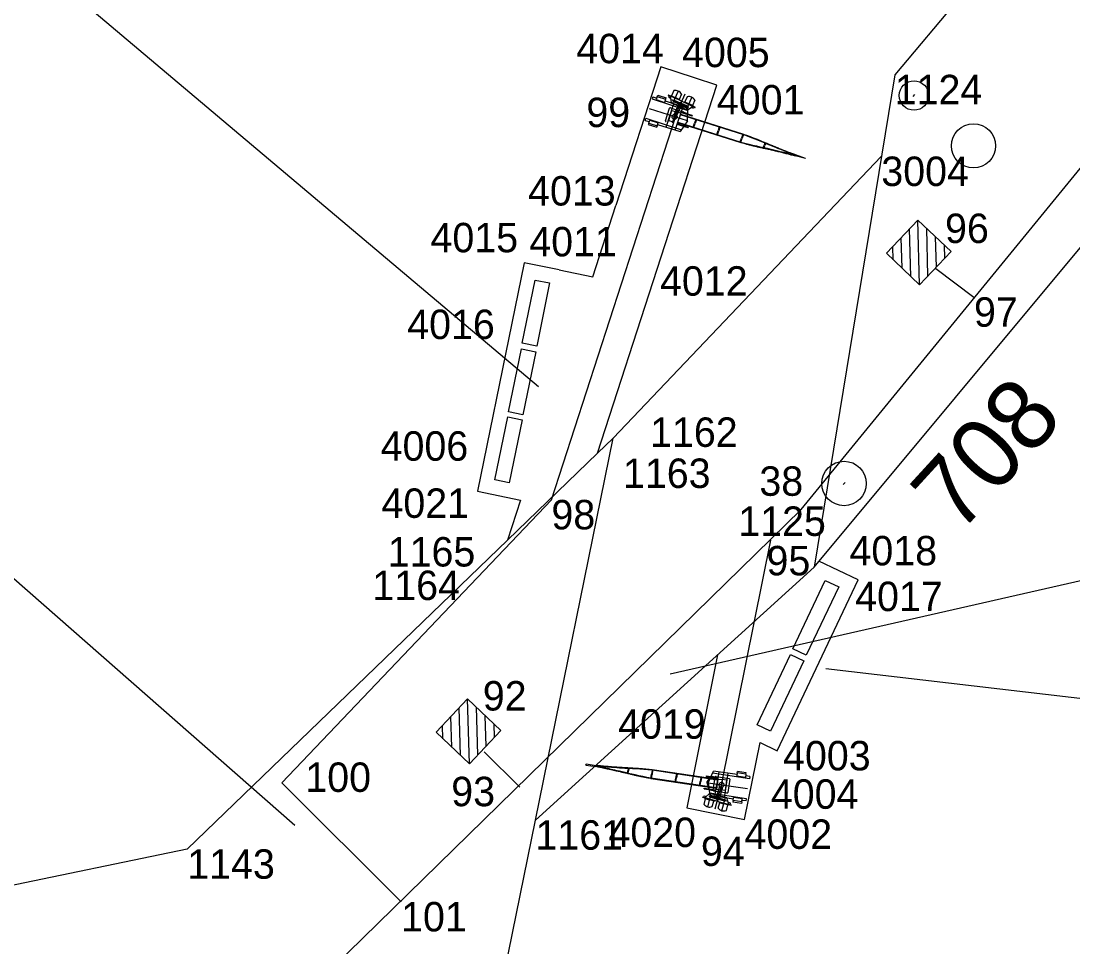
# Model space of a CAD drawing. Extents: x -678683 to -677755, y -1006946 to -1005971.
# Drawn here: x -678303.02 to -678267.29, y -1006518.8 to -1006487.34 of the extents above; entities that cross this region are included whole.
import ezdxf

# ---------------------------------------------------------------- set-up
doc = ezdxf.new("R2010")
doc.units = 0
for name, color, linetype in [('Default', 7, 'Continuous'), ('Dočasný zábor - do 1 roku', 7, 'Continuous'), ('Dočasný zábor_body', 7, 'Continuous'), ('OSY', 7, 'Continuous'), ('SSZT nové - lomové body', 7, 'Continuous'), ('SSZT_nové', 7, 'Continuous'), ('Stávající ŽBP', 7, 'Continuous'), ('SŽDC', 7, 'Continuous'), ('SŽDC - body', 7, 'Continuous'), ('Trvalý zábor', 7, 'Continuous'), ('Trvalý zábor - body', 7, 'Continuous'), ('Vrstva 7', 7, 'Continuous')]:
    doc.layers.add(name, color=color, linetype=linetype)

# ---------------------------------------------------------------- blocks, each defined once
blk = doc.blocks.new('AZD97_VYSTRAZNIK')
at = {"layer": 'Default'}
for p, q in [((-34, -7.5), (-24, 8)), ((-24, 8), (0, 8)), ((-20, 2), (0, 2)), ((24, 8), (0, 8)), ((20, 2), (0, 2)), ((34, -7.5), (24, 8)), ((0, -7.5), (-40, -7.5)), ((-40, -7.5), (-40, -8)), ((0, -8), (-40, -8)), ((-36.9, -7.5), (-36.9, -3)), ((-36.9, -3), (-31.1, -3)), ((-34, -8), (-34, -9.5)), ((-34, -9.5), (-20, -9.5)), ((-31.5, -25.2), (-31.5, -9.5)), ((-20, -2), (0, -2)), ((-6, -9.5), (-20, -9.5)), ((-8.5, -25.2), (-8.5, -9.5)), ((-6, -8), (-6, -9.5)), ((20, -2), (0, -2)), ((0, -7.5), (40, -7.5)), ((0, -8), (40, -8)), ((6, -8), (6, -9.5)), ((6, -9.5), (20, -9.5)), ((8.5, -25.2), (8.5, -9.5)), ((34, -9.5), (20, -9.5)), ((36.9, -3), (31.1, -3)), ((31.5, -25.2), (31.5, -9.5)), ((34, -8), (34, -9.5)), ((36.9, -7.5), (36.9, -3)), ((40, -7.5), (40, -8))]:
    blk.add_line(p, q, dxfattribs=at)
for centre in [(-20, 0), (20, 0)]:
    blk.add_circle(centre, 2, dxfattribs=at)
for centre, start, end in [((-20, -9.5), 233.8612, 270), ((-20, -9.5), 270, 306.1388), ((20, -9.5), 233.8612, 270), ((20, -9.5), 270, 306.1388)]:
    blk.add_arc(centre, 19.5, start, end, dxfattribs=at)
at = {"layer": 'OSY'}
for p, q in [((-24.8, 0), (25.7, 0)), ((-20, -29), (-20, 8)), ((0, 8), (0, -29.7)), ((20, -29), (20, 8))]:
    blk.add_line(p, q, dxfattribs=at)
blk = doc.blocks.new('AZD97_DRZAK')
at = {"layer": 'Default'}
for p, q in [((-4, -5.3), (-4, -38.3)), ((-0.7, -7.4), (-0.7, -6.6)), ((0.6, -7.4), (0.6, -6.6)), ((4, -5.3), (4, -38.3))]:
    blk.add_line(p, q, dxfattribs=at)
for centre, radius, start, end in [((0, 0), 6.65, 233.0223, 306.9777), ((0, 0), 7.5, 237.769, 270), ((0, 0), 7.5, 270, 302.231), ((0, -38.3), 4, 180, 0)]:
    blk.add_arc(centre, radius, start, end, dxfattribs=at)
at = {"layer": 'OSY'}
for p, q in [((0, 6.6), (0, -42.3)), ((-6.7, 0), (6.6, 0)), ((-4, -38.3), (4, -38.3))]:
    blk.add_line(p, q, dxfattribs=at)
blk = doc.blocks.new('AZD99_KŘÍDLA')
at = {"layer": 'Default'}
for p, q in [((-46, 0), (-34, 42)), ((47, 42), (-34, 42)), ((-16, 42), (-16, 0)), ((47, 47.5), (47, 52.5)), ((77, 52.5), (47, 52.5)), ((77, 47.5), (47, 47.5)), ((47, 47.5), (47, 36.5)), ((77, 36.5), (47, 36.5)), ((77, 47.5), (77, 52.5)), ((77, 47.5), (77, 36.5)), ((91, 42), (77, 42)), ((91, 42), (91, 34.5)), ((-56, 22), (-16, 22)), ((-56, 22), (-56, 20)), ((-56, 20), (-16, 20)), ((-46, 0), (-34, -42)), ((91, 34.5), (-36.2, 34.5)), ((-16, -42), (-16, 0)), ((-56, -20), (-16, -20)), ((-56, -22), (-56, -20)), ((-56, -22), (-16, -22)), ((91, -34.5), (-36.2, -34.5)), ((91, -42), (91, -34.5)), ((47, -42), (-34, -42)), ((77, -36.5), (47, -36.5)), ((47, -47.5), (47, -36.5)), ((77, -47.5), (47, -47.5)), ((47, -47.5), (47, -52.5)), ((77, -52.5), (47, -52.5)), ((77, -47.5), (77, -36.5)), ((91, -42), (77, -42)), ((77, -47.5), (77, -52.5))]:
    blk.add_line(p, q, dxfattribs=at)
at = {"layer": 'OSY'}
for p, q in [((16, 42), (16, -42)), ((-46, 0), (89, 0)), ((0, 21.9), (0, -22.2))]:
    blk.add_line(p, q, dxfattribs=at)

msp = doc.modelspace()

# ---------------------------------------------------------------- linework, layer by layer
at = {"layer": 'Dočasný zábor - do 1 roku'}
for p, q in [((-678281.283, -1006488.901), (-678282.811, -1006493.613)), ((-678280.139, -1006489.272), (-678281.283, -1006488.901)), ((-678279.381, -1006489.517), (-678280.139, -1006489.272)), ((-678283.435, -1006502.026), (-678279.381, -1006489.517)), ((-678283.595, -1006496.033), (-678282.811, -1006493.613)), ((-678285.921, -1006495.555), (-678286.341, -1006497.603)), ((-678284.743, -1006495.797), (-678285.921, -1006495.555)), ((-678284.743, -1006495.797), (-678283.595, -1006496.033)), ((-678286.341, -1006497.603), (-678287.515, -1006503.316)), ((-678287.515, -1006503.316), (-678286.053, -1006503.616)), ((-678286.053, -1006503.616), (-678286.495, -1006504.981)), ((-678274.577, -1006506.322), (-678275.913, -1006505.69)), ((-678277.328, -1006512.133), (-678274.577, -1006506.322)), ((-678279.356, -1006508.868), (-678280.402, -1006514.072)), ((-678278.442, -1006514.466), (-678277.916, -1006511.854)), ((-678277.916, -1006511.854), (-678277.328, -1006512.133)), ((-678280.402, -1006514.072), (-678278.442, -1006514.466))]:
    msp.add_line(p, q, dxfattribs=at)
at = {"layer": 'Dočasný zábor_body'}
for p, q in [((-678281.283, -1006488.901), (-678281.283, -1006488.901)), ((-678280.139, -1006489.272), (-678280.139, -1006489.272)), ((-678279.381, -1006489.517), (-678279.381, -1006489.517)), ((-678282.811, -1006493.613), (-678282.811, -1006493.613)), ((-678282.811, -1006493.613), (-678282.811, -1006493.613)), ((-678285.921, -1006495.555), (-678285.921, -1006495.555)), ((-678284.743, -1006495.797), (-678284.743, -1006495.797)), ((-678283.595, -1006496.033), (-678283.595, -1006496.033)), ((-678286.341, -1006497.603), (-678286.341, -1006497.603)), ((-678287.515, -1006503.316), (-678287.515, -1006503.316)), ((-678286.053, -1006503.616), (-678286.053, -1006503.616)), ((-678275.913, -1006505.69), (-678275.913, -1006505.69)), ((-678274.577, -1006506.322), (-678274.577, -1006506.322)), ((-678279.356, -1006508.868), (-678279.356, -1006508.868)), ((-678277.916, -1006511.854), (-678277.916, -1006511.854)), ((-678277.328, -1006512.133), (-678277.328, -1006512.133)), ((-678280.402, -1006514.072), (-678280.402, -1006514.072)), ((-678278.442, -1006514.466), (-678278.442, -1006514.466))]:
    msp.add_line(p, q, dxfattribs=at)
at = {"layer": 'SSZT nové - lomové body'}
for p, q in [((-678280.64, -1006490.16), (-678280.64, -1006490.16)), ((-678271.945, -1006495.744), (-678271.945, -1006495.744)), ((-678270.648, -1006496.728), (-678270.648, -1006496.728)), ((-678285, -1006503.611), (-678285, -1006503.611)), ((-678276.518, -1006503.932), (-678276.518, -1006503.932)), ((-678277.553, -1006504.979), (-678277.553, -1006504.979)), ((-678287.288, -1006512.164), (-678287.288, -1006512.164)), ((-678294.158, -1006513.226), (-678294.158, -1006513.226)), ((-678279.225, -1006513.289), (-678279.225, -1006513.289)), ((-678286.073, -1006513.373), (-678286.073, -1006513.373)), ((-678290.107, -1006517.269), (-678290.107, -1006517.269))]:
    msp.add_line(p, q, dxfattribs=at)
at = {"layer": 'SSZT_nové'}
for p, q in [((-678319.244, -1006471.244), (-678285.442, -1006499.753)), ((-678285, -1006503.611), (-678280.64, -1006490.16)), ((-678281.125, -1006490.734), (-678280.987, -1006490.305)), ((-678281.014, -1006490.717), (-678280.907, -1006490.383)), ((-678280.956, -1006490.289), (-678280.754, -1006490.354)), ((-678280.907, -1006490.383), (-678280.764, -1006490.429)), ((-678280.622, -1006490.475), (-678280.764, -1006490.429)), ((-678280.754, -1006490.354), (-678280.527, -1006490.426)), ((-678280.593, -1006490.421), (-678280.666, -1006490.645)), ((-678280.371, -1006490.492), (-678280.593, -1006490.421)), ((-678281.014, -1006490.717), (-678280.871, -1006490.762)), ((-678280.713, -1006490.79), (-678278.571, -1006491.471)), ((-678280.709, -1006490.777), (-678278.566, -1006491.457)), ((-678280.619, -1006490.502), (-678280.666, -1006490.646)), ((-678280.623, -1006490.515), (-678278.481, -1006491.196)), ((-678280.619, -1006490.502), (-678278.477, -1006491.183)), ((-678280.096, -1006490.683), (-678280.139, -1006490.814)), ((-678280.074, -1006490.69), (-678280.117, -1006490.821)), ((-678280.181, -1006490.944), (-678280.139, -1006490.814)), ((-678280.159, -1006490.951), (-678280.117, -1006490.821)), ((-678279.385, -1006491.197), (-678279.342, -1006491.067)), ((-678279.363, -1006491.204), (-678279.32, -1006491.074)), ((-678279.3, -1006490.936), (-678279.342, -1006491.067)), ((-678279.278, -1006490.943), (-678279.32, -1006491.074)), ((-678278.588, -1006491.451), (-678278.546, -1006491.32)), ((-678278.566, -1006491.457), (-678278.524, -1006491.327)), ((-678278.503, -1006491.189), (-678278.546, -1006491.32)), ((-678278.481, -1006491.196), (-678278.524, -1006491.327)), ((-678277.751, -1006491.484), (-678277.777, -1006491.564)), ((-678277.729, -1006491.493), (-678277.755, -1006491.571)), ((-678277.803, -1006491.644), (-678277.777, -1006491.564)), ((-678277.78, -1006491.649), (-678277.755, -1006491.571)), ((-678277.014, -1006491.829), (-678277.008, -1006491.808)), ((-678277.001, -1006491.788), (-678277.008, -1006491.808)), ((-678276.992, -1006491.834), (-678276.986, -1006491.815)), ((-678276.979, -1006491.796), (-678276.986, -1006491.815)), ((-678276.366, -1006492.017), (-678276.717, -1006491.922)), ((-678276.366, -1006492.017), (-678276.705, -1006491.883)), ((-678272.494, -1006496.303), (-678272.553, -1006494.103)), ((-678273.093, -1006495.735), (-678273.121, -1006494.702)), ((-678272.793, -1006496.019), (-678272.837, -1006494.402)), ((-678272.21, -1006496.003), (-678272.254, -1006494.386)), ((-678271.926, -1006495.703), (-678271.954, -1006494.671)), ((-678273.392, -1006495.451), (-678273.405, -1006495.002)), ((-678271.643, -1006495.404), (-678271.655, -1006494.954)), ((-678271.945, -1006495.744), (-678270.648, -1006496.728)), ((-678311.879, -1006498.718), (-678293.712, -1006514.658)), ((-678285, -1006503.611), (-678294.158, -1006513.226)), ((-678280.963, -1006509.518), (-678258.777, -1006504.475)), ((-678279.225, -1006513.289), (-678277.553, -1006504.979)), ((-678275.682, -1006509.338), (-678242.476, -1006513.226)), ((-678287.788, -1006512.573), (-678287.848, -1006510.373)), ((-678288.088, -1006512.289), (-678288.132, -1006510.673)), ((-678287.505, -1006512.273), (-678287.549, -1006510.657)), ((-678288.388, -1006512.005), (-678288.416, -1006510.973)), ((-678287.221, -1006511.974), (-678287.249, -1006510.941)), ((-678288.687, -1006511.722), (-678288.699, -1006511.272)), ((-678286.937, -1006511.674), (-678286.949, -1006511.224)), ((-678287.288, -1006512.164), (-678286.073, -1006513.373)), ((-678283.828, -1006512.594), (-678283.826, -1006512.581)), ((-678283.826, -1006512.581), (-678283.484, -1006512.632)), ((-678283.83, -1006512.608), (-678283.832, -1006512.621)), ((-678283.832, -1006512.621), (-678283.49, -1006512.672)), ((-678283.205, -1006512.714), (-678283.202, -1006512.694)), ((-678283.199, -1006512.674), (-678283.202, -1006512.694)), ((-678283.182, -1006512.718), (-678283.179, -1006512.698)), ((-678283.176, -1006512.677), (-678283.179, -1006512.698)), ((-678282.416, -1006512.894), (-678282.404, -1006512.813)), ((-678282.391, -1006512.732), (-678282.404, -1006512.813)), ((-678282.394, -1006512.899), (-678282.381, -1006512.816)), ((-678282.368, -1006512.733), (-678282.381, -1006512.816)), ((-678281.627, -1006513.067), (-678281.605, -1006512.931)), ((-678281.584, -1006512.795), (-678281.605, -1006512.931)), ((-678281.604, -1006513.071), (-678281.583, -1006512.935)), ((-678279.361, -1006513.126), (-678281.584, -1006512.795)), ((-678281.562, -1006512.799), (-678281.583, -1006512.935)), ((-678279.359, -1006513.112), (-678281.582, -1006512.782)), ((-678280.758, -1006512.918), (-678280.779, -1006513.054)), ((-678280.735, -1006512.922), (-678280.756, -1006513.057)), ((-678294.158, -1006513.226), (-678290.107, -1006517.269)), ((-678279.405, -1006513.411), (-678281.629, -1006513.081)), ((-678279.403, -1006513.397), (-678281.627, -1006513.067)), ((-678280.8, -1006513.19), (-678280.779, -1006513.054)), ((-678280.777, -1006513.193), (-678280.756, -1006513.057)), ((-678279.973, -1006513.313), (-678279.952, -1006513.177)), ((-678279.931, -1006513.041), (-678279.952, -1006513.177)), ((-678279.951, -1006513.316), (-678279.929, -1006513.18)), ((-678279.908, -1006513.044), (-678279.929, -1006513.18)), ((-678279.724, -1006513.211), (-678279.575, -1006512.994)), ((-678279.724, -1006513.211), (-678279.648, -1006513.461)), ((-678279.575, -1006512.994), (-678279.346, -1006513.028)), ((-678279.505, -1006513.472), (-678279.438, -1006513.027)), ((-678279.418, -1006513.495), (-678279.382, -1006513.262)), ((-678279.409, -1006513.006), (-678279.174, -1006513.042)), ((-678279.405, -1006513.411), (-678279.382, -1006513.262)), ((-678279.346, -1006513.092), (-678279.398, -1006513.438)), ((-678279.346, -1006513.028), (-678279.382, -1006513.261)), ((-678279.359, -1006513.112), (-678279.382, -1006513.262)), ((-678279.346, -1006513.092), (-678279.198, -1006513.114)), ((-678279.05, -1006513.136), (-678279.198, -1006513.114)), ((-678279.174, -1006513.042), (-678278.964, -1006513.073)), ((-678279.05, -1006513.136), (-678279.102, -1006513.482)), ((-678278.943, -1006513.102), (-678279.01, -1006513.547)), ((-678279.648, -1006513.461), (-678279.418, -1006513.495)), ((-678279.249, -1006513.536), (-678279.484, -1006513.501)), ((-678279.398, -1006513.438), (-678279.25, -1006513.46)), ((-678279.102, -1006513.482), (-678279.25, -1006513.46)), ((-678279.039, -1006513.568), (-678279.249, -1006513.536))]:
    msp.add_line(p, q, dxfattribs=at)
for points in [[(-678276.518, -1006503.932), (-678257.417, -1006480.575), (-678238.833, -1006456.747), (-678223.794, -1006437.464), (-678213.311, -1006424.022), (-678199.433, -1006408.271)], [(-678506.624, -1006791.938), (-678466.12, -1006753.227), (-678449.329, -1006728.75), (-678428.753, -1006695.612), (-678421.07, -1006681.971), (-678401.666, -1006635.236), (-678393.87, -1006623.108), (-678390.132, -1006617.261), (-678380.001, -1006603.755), (-678359.836, -1006584.701), (-678339.66, -1006565.68), (-678276.518, -1006503.932), (-678276.518, -1006503.932)]]:
    msp.add_lwpolyline(points, dxfattribs=at)
for points in [[(-678273.623, -1006495.233), (-678272.553, -1006494.103), (-678271.424, -1006495.173), (-678272.494, -1006496.303)], [(-678285.555, -1006496.141), (-678285.061, -1006496.242), (-678285.501, -1006498.384), (-678285.995, -1006498.282)], [(-678286.022, -1006498.481), (-678285.528, -1006498.583), (-678285.968, -1006500.724), (-678286.462, -1006500.623)], [(-678286.485, -1006500.785), (-678285.991, -1006500.887), (-678286.431, -1006503.028), (-678286.925, -1006502.927)], [(-678275.699, -1006506.344), (-678275.243, -1006506.56), (-678276.345, -1006508.888), (-678276.8, -1006508.672)], [(-678276.878, -1006508.866), (-678276.422, -1006509.082), (-678277.554, -1006511.472), (-678278.009, -1006511.257)], [(-678288.918, -1006511.503), (-678287.848, -1006510.373), (-678286.718, -1006511.443), (-678287.788, -1006512.573)]]:
    msp.add_lwpolyline(points, close=True, dxfattribs=at)
for centre in [(-678280.818, -1006490.596), (-678279.224, -1006513.287)]:
    msp.add_circle(centre, 0.0831, dxfattribs=at)
for centre, start, end in [((-678280.964, -1006490.313), 72.2544, 162.2544), ((-678280.535, -1006490.45), 342.2544, 72.2544), ((-678281.101, -1006490.741), 162.2544, 252.2544), ((-678279.413, -1006513.031), 81.4339, 171.4339), ((-678278.968, -1006513.098), 351.4339, 81.4339), ((-678279.48, -1006513.476), 171.4339, 261.4339), ((-678279.035, -1006513.543), 261.4339, 351.4339)]:
    msp.add_arc(centre, 0.025, start, end, dxfattribs=at)
for points in [[(-678278.568, -1006491.47), (-678278.485, -1006491.492), (-678278.402, -1006491.515), (-678278.275, -1006491.547), (-678278.232, -1006491.558), (-678278.146, -1006491.58), (-678278.103, -1006491.59), (-678277.974, -1006491.62), (-678277.888, -1006491.639), (-678277.727, -1006491.675), (-678277.652, -1006491.691), (-678277.499, -1006491.726), (-678277.419, -1006491.744), (-678277.261, -1006491.781), (-678277.182, -1006491.8), (-678277.056, -1006491.832), (-678277.01, -1006491.844), (-678276.917, -1006491.868), (-678276.871, -1006491.881), (-678276.788, -1006491.903), (-678276.752, -1006491.913), (-678276.716, -1006491.923)], [(-678278.566, -1006491.457), (-678278.198, -1006491.553), (-678277.512, -1006491.709), (-678277.014, -1006491.829), (-678276.713, -1006491.909), (-678278.566, -1006491.457), (-678276.713, -1006491.909)], [(-678278.481, -1006491.197), (-678278.126, -1006491.331), (-678277.477, -1006491.599), (-678277.001, -1006491.788), (-678276.709, -1006491.896), (-678278.481, -1006491.197), (-678276.709, -1006491.896)], [(-678278.476, -1006491.185), (-678278.395, -1006491.214), (-678278.314, -1006491.244), (-678278.191, -1006491.291), (-678278.15, -1006491.307), (-678278.068, -1006491.339), (-678278.027, -1006491.355), (-678277.904, -1006491.405), (-678277.822, -1006491.439), (-678277.671, -1006491.503), (-678277.601, -1006491.532), (-678277.455, -1006491.593), (-678277.38, -1006491.624), (-678277.229, -1006491.685), (-678277.154, -1006491.715), (-678277.033, -1006491.761), (-678276.989, -1006491.778), (-678276.899, -1006491.812), (-678276.854, -1006491.829), (-678276.774, -1006491.858), (-678276.738, -1006491.871), (-678276.703, -1006491.884)], [(-678281.63, -1006513.079), (-678281.715, -1006513.063), (-678281.8, -1006513.046), (-678281.928, -1006513.02), (-678281.971, -1006513.011), (-678282.058, -1006512.992), (-678282.101, -1006512.982), (-678282.23, -1006512.953), (-678282.316, -1006512.932), (-678282.476, -1006512.894), (-678282.55, -1006512.876), (-678282.703, -1006512.839), (-678282.782, -1006512.82), (-678282.94, -1006512.784), (-678283.02, -1006512.767), (-678283.146, -1006512.74), (-678283.193, -1006512.73), (-678283.287, -1006512.711), (-678283.334, -1006512.702), (-678283.418, -1006512.686), (-678283.455, -1006512.679), (-678283.492, -1006512.672)], [(-678281.626, -1006513.066), (-678281.999, -1006512.991), (-678282.682, -1006512.83), (-678283.182, -1006512.718), (-678283.488, -1006512.659), (-678281.626, -1006513.066), (-678283.488, -1006512.659)], [(-678281.584, -1006512.796), (-678281.963, -1006512.76), (-678282.665, -1006512.715), (-678283.176, -1006512.677), (-678283.486, -1006512.645), (-678281.584, -1006512.796), (-678283.486, -1006512.645)], [(-678281.584, -1006512.783), (-678281.67, -1006512.774), (-678281.756, -1006512.765), (-678281.886, -1006512.753), (-678281.93, -1006512.749), (-678282.019, -1006512.742), (-678282.063, -1006512.739), (-678282.195, -1006512.729), (-678282.283, -1006512.724), (-678282.448, -1006512.714), (-678282.524, -1006512.71), (-678282.681, -1006512.701), (-678282.762, -1006512.696), (-678282.925, -1006512.684), (-678283.006, -1006512.678), (-678283.135, -1006512.667), (-678283.182, -1006512.662), (-678283.278, -1006512.653), (-678283.326, -1006512.648), (-678283.411, -1006512.639), (-678283.448, -1006512.635), (-678283.485, -1006512.631)]]:
    msp.add_open_spline(points, degree=3, dxfattribs=at)
at = {"layer": 'Stávající ŽBP'}
msp.add_line((-678275.096, -1006503.09), (-678275.028, -1006503.016), dxfattribs=at)
msp.add_circle((-678275.062, -1006503.053), 0.756, dxfattribs=at)
at = {"layer": 'SŽDC'}
for p, q in [((-678259.32, -1006472.44), (-678273.34, -1006489.17)), ((-678273.34, -1006489.17), (-678276.08, -1006505.89)), ((-678276.08, -1006505.89), (-678265.21, -1006492.84)), ((-678285.543, -1006514.493), (-678282.9, -1006501.51)), ((-678282.9, -1006501.51), (-678283.435, -1006502.026)), ((-678283.435, -1006502.026), (-678286.495, -1006504.981)), ((-678286.495, -1006504.981), (-678297.37, -1006515.48)), ((-678288.96, -1006531.28), (-678285.543, -1006514.493)), ((-678297.37, -1006515.48), (-678306.89, -1006517.45))]:
    msp.add_line(p, q, dxfattribs=at)
at = {"layer": 'SŽDC - body'}
for p, q in [((-678273.34, -1006489.17), (-678273.34, -1006489.17)), ((-678282.9, -1006501.51), (-678282.9, -1006501.51)), ((-678283.435, -1006502.026), (-678283.435, -1006502.026)), ((-678286.495, -1006504.981), (-678286.495, -1006504.981)), ((-678286.495, -1006504.981), (-678286.495, -1006504.981)), ((-678276.08, -1006505.89), (-678276.08, -1006505.89)), ((-678285.543, -1006514.493), (-678285.543, -1006514.493)), ((-678297.37, -1006515.48), (-678297.37, -1006515.48))]:
    msp.add_line(p, q, dxfattribs=at)
at = {"layer": 'Trvalý zábor'}
for p, q in [((-678282.9, -1006501.51), (-678273.795, -1006491.947)), ((-678276.08, -1006505.89), (-678285.543, -1006514.493))]:
    msp.add_line(p, q, dxfattribs=at)
at = {"layer": 'Trvalý zábor - body'}
msp.add_line((-678273.795, -1006491.947), (-678273.795, -1006491.947), dxfattribs=at)
at = {"layer": 'Vrstva 7'}
msp.add_line((-678272.718, -1006489.912), (-678272.652, -1006489.836), dxfattribs=at)
for centre, radius in [((-678272.685, -1006489.874), 0.5), ((-678270.665, -1006491.581), 0.75)]:
    msp.add_circle(centre, radius, dxfattribs=at)

# ---------------------------------------------------------------- block references
at = {"layer": 'SSZT_nové'}
for name, p, xscale, yscale, rotation in [('AZD97_VYSTRAZNIK', (-678280.614, -1006490.156), 0.012499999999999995, 0.012499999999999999, 155.69273437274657), ('AZD99_KŘÍDLA', (-678280.818, -1006490.596), 0.010000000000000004, 0.010000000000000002, 162.25443298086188), ('AZD97_DRZAK', (-678280.817, -1006490.594), 0.012499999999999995, 0.012499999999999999, 155.41189516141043), ('AZD99_KŘÍDLA', (-678279.224, -1006513.287), 0.010000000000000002, 0.010000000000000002, -8.566093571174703), ('AZD97_DRZAK', (-678279.225, -1006513.289), 0.012499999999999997, 0.012499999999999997, -15.408631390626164), ('AZD97_VYSTRAZNIK', (-678279.355, -1006513.753), 0.012499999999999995, 0.012499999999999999, -15.127792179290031)]:
    msp.add_blockref(name, p, dxfattribs=dict(at, xscale=xscale, yscale=yscale, rotation=rotation))

# ---------------------------------------------------------------- texts
at = {"layer": 'Dočasný zábor_body'}
for s, p in [('4014', (-678284.156, -1006488.776)), ('4005', (-678280.563, -1006488.909)), ('4001', (-678279.381, -1006490.517)), ('4013', (-678285.794, -1006493.611)), ('4015', (-678289.108, -1006495.199)), ('4011', (-678285.752, -1006495.337)), ('4012', (-678281.312, -1006496.673)), ('4016', (-678289.899, -1006498.146)), ('4006', (-678290.801, -1006502.279)), ('4021', (-678290.773, -1006504.221)), ('4018', (-678274.877, -1006505.834)), ('4017', (-678274.684, -1006507.388)), ('4019', (-678282.735, -1006511.723)), ('4003', (-678277.133, -1006512.799)), ('4004', (-678277.548, -1006514.103)), ('4020', (-678283.064, -1006515.402)), ('4002', (-678278.442, -1006515.466))]:
    msp.add_text(s, height=1, dxfattribs=at).set_placement(p)
at = {"layer": 'SSZT nové - lomové body'}
for s, p in [('99', (-678283.814, -1006490.946)), ('96', (-678271.631, -1006494.884)), ('97', (-678270.648, -1006497.728)), ('38', (-678277.937, -1006503.471)), ('98', (-678285, -1006504.611)), ('95', (-678277.695, -1006506.173)), ('92', (-678287.331, -1006510.765)), ('100', (-678293.359, -1006513.53)), ('93', (-678288.403, -1006514.016)), ('94', (-678279.923, -1006516.045)), ('101', (-678290.107, -1006518.269))]:
    msp.add_text(s, height=1, dxfattribs=at).set_placement(p)
at = {"layer": 'Stávající ŽBP'}
msp.add_text('708', height=2.4, rotation=47.549, dxfattribs=at).set_placement((-678271.17, -1006504.815))
at = {"layer": 'SŽDC - body'}
for s, p in [('1124', (-678273.34, -1006490.17)), ('1162', (-678281.65, -1006501.809)), ('1163', (-678282.57, -1006503.205)), ('1125', (-678278.654, -1006504.833)), ('1165', (-678290.561, -1006505.873)), ('1164', (-678291.083, -1006507.012)), ('1161', (-678285.543, -1006515.493)), ('1143', (-678297.37, -1006516.48))]:
    msp.add_text(s, height=1, dxfattribs=at).set_placement(p)
at = {"layer": 'Trvalý zábor - body'}
msp.add_text('3004', height=1, dxfattribs=at).set_placement((-678273.795, -1006492.947))

doc.saveas('drawing.dxf')
